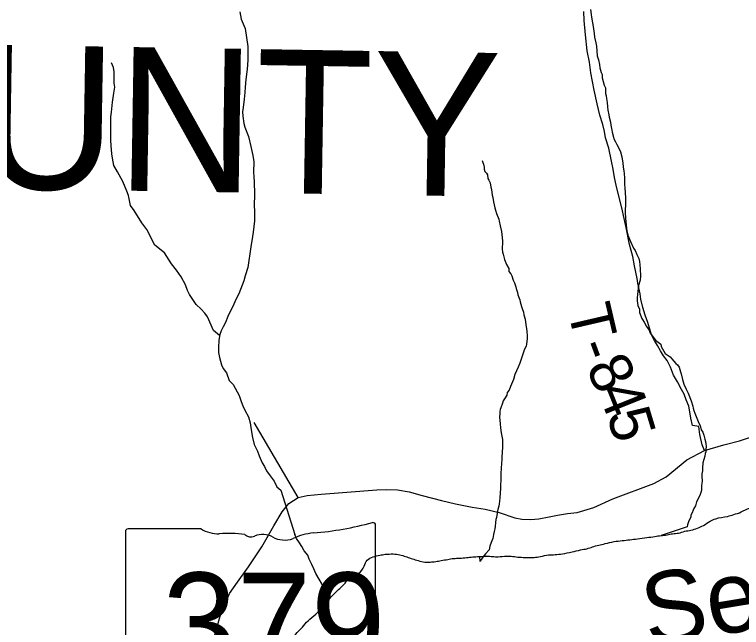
# Model space of a CAD drawing. Extents: x 0 to 191, y 0 to 55.
# Drawn here: x 149.0114 to 149.4907, y 21.5453 to 21.9492 of the extents above; entities that cross this region are included whole.
import ezdxf

# ---------------------------------------------------------------- set-up
doc = ezdxf.new("R2010")
doc.units = 0
for name, color, linetype in [('GM_X_County_Text', 7, 'Continuous'), ('GM_X_Minor_River', 7, 'Continuous'), ('GM_X_Minor_River_Text', 7, 'Continuous'), ('GM_X_State_Location', 7, 'Continuous'), ('GM_X_State_Route', 7, 'Continuous'), ('GM_X_State_Shield', 7, 'Continuous'), ('GM_X_Township_Road', 7, 'Continuous'), ('GM_X_Township_Road_Text', 7, 'Continuous')]:
    doc.layers.add(name, color=color, linetype=linetype)

msp = doc.modelspace()

# ---------------------------------------------------------------- linework, layer by layer
at = {"layer": 'GM_X_Minor_River'}
for points in [[(149.39103, 21.9526), (149.39158, 21.94918), (149.39176, 21.94747), (149.39249, 21.94386), (149.39285, 21.94139), (149.39358, 21.93682), (149.39376, 21.93435), (149.39468, 21.93055), (149.39505, 21.92846), (149.39558, 21.922), (149.39632, 21.91934), (149.39706, 21.91629), (149.39723, 21.9142), (149.39816, 21.91097), (149.39872, 21.90964), (149.3989, 21.90755), (149.40019, 21.90279), (149.40094, 21.90089), (149.40093, 21.89975), (149.40111, 21.89709), (149.40147, 21.89557), (149.40165, 21.89386), (149.40202, 21.89119), (149.40238, 21.88834), (149.40255, 21.88625), (149.40329, 21.88321), (149.40347, 21.8815), (149.40421, 21.87827), (149.40458, 21.87637), (149.40512, 21.87313), (149.40549, 21.87161), (149.40623, 21.86838), (149.4066, 21.86724), (149.40754, 21.86533), (149.40848, 21.86362), (149.40942, 21.86209), (149.41091, 21.85866), (149.41184, 21.85543), (149.41238, 21.85125), (149.41274, 21.84878), (149.41311, 21.84593), (149.41329, 21.8446), (149.41346, 21.84118), (149.41364, 21.84004), (149.41362, 21.83681), (149.4138, 21.83548), (149.41396, 21.8313), (149.41413, 21.82883), (149.4141, 21.82351), (149.41389, 21.82067), (149.41388, 21.81877), (149.41423, 21.81497), (149.41476, 21.80813), (149.41513, 21.80661), (149.41568, 21.80394), (149.41755, 21.79975), (149.41942, 21.79537), (149.42055, 21.79366), (149.42167, 21.79118), (149.42298, 21.78851), (149.42354, 21.78642), (149.42371, 21.78433), (149.42388, 21.78167), (149.42404, 21.77673), (149.42384, 21.77427), (149.42286, 21.77067), (149.42266, 21.76858), (149.42207, 21.76478), (149.42186, 21.76251)], [(149.15985, 21.95111), (149.16068, 21.94618), (149.16342, 21.93995), (149.16529, 21.9282), (149.16523, 21.91927), (149.16476, 21.91318), (149.16391, 21.90633), (149.16341, 21.90138), (149.16327, 21.89796), (149.16277, 21.8934), (149.1621, 21.88788), (149.16176, 21.88502), (149.16199, 21.88217), (149.16263, 21.87743), (149.16323, 21.87497), (149.16559, 21.86893), (149.1672, 21.8623), (149.16842, 21.85643), (149.16905, 21.85226), (149.16896, 21.84542), (149.16919, 21.84238), (149.16943, 21.83896), (149.16955, 21.83079), (149.16928, 21.82319), (149.16952, 21.81978), (149.16962, 21.81332), (149.16878, 21.80589), (149.16826, 21.80285), (149.16722, 21.79618), (149.16515, 21.78248), (149.16352, 21.77713), (149.16263, 21.7737), (149.15935, 21.76511), (149.15713, 21.76109), (149.15549, 21.75726), (149.15401, 21.75439), (149.15199, 21.75019), (149.15035, 21.74636), (149.14888, 21.74349), (149.14759, 21.74081), (149.14668, 21.73833), (149.14616, 21.73471), (149.14586, 21.72977), (149.14591, 21.72654), (149.14652, 21.72313), (149.14773, 21.7184), (149.1489, 21.71594), (149.15102, 21.71312), (149.1528, 21.70802), (149.15549, 21.7054), (149.15938, 21.69823), (149.16076, 21.69426), (149.16193, 21.69143), (149.1633, 21.68841), (149.16564, 21.68407), (149.16664, 21.68009), (149.16725, 21.67706), (149.16767, 21.67422), (149.1683, 21.67043), (149.16931, 21.66588), (149.17145, 21.66154), (149.17264, 21.65833), (149.17459, 21.6538), (149.17614, 21.65135), (149.17751, 21.64852), (149.17983, 21.64513), (149.18253, 21.64175), (149.18429, 21.63797), (149.18697, 21.63573), (149.1962, 21.60661)], [(149.14658, 21.73764), (149.14248, 21.74093), (149.13856, 21.75), (149.13682, 21.75244), (149.13432, 21.75507), (149.13106, 21.75806), (149.1268, 21.76465), (149.12544, 21.76729), (149.12406, 21.77107), (149.12133, 21.77635), (149.11824, 21.78068), (149.11496, 21.78501), (149.11013, 21.79216), (149.10381, 21.7972), (149.09855, 21.80757), (149.09527, 21.8119), (149.09023, 21.82019), (149.08791, 21.82338), (149.08649, 21.83001), (149.0855, 21.83285), (149.08276, 21.83927), (149.07926, 21.84568), (149.07693, 21.84964), (149.07591, 21.85457), (149.07549, 21.85741), (149.07504, 21.86291), (149.0748, 21.86633), (149.07488, 21.87355), (149.07476, 21.88172), (149.07528, 21.88496), (149.07594, 21.89142), (149.0768, 21.89751), (149.0775, 21.90132), (149.07708, 21.90398), (149.07698, 21.91158), (149.07655, 21.91442), (149.07519, 21.91744)], [(149.3198, 21.85301), (149.32017, 21.85168), (149.32054, 21.85054), (149.32091, 21.84864), (149.32109, 21.84731), (149.32146, 21.84578), (149.32259, 21.84464), (149.32315, 21.84349), (149.32352, 21.84121), (149.32408, 21.84007), (149.32502, 21.83835), (149.32538, 21.8355), (149.32575, 21.83398), (149.32629, 21.83018), (149.32666, 21.82866), (149.32721, 21.82581), (149.32795, 21.82182), (149.32851, 21.82029), (149.32906, 21.8182), (149.33074, 21.81439), (149.33093, 21.81306), (149.33148, 21.81002), (149.3324, 21.80621), (149.33258, 21.80431), (149.33312, 21.80013), (149.33311, 21.79823), (149.3329, 21.79596), (149.33289, 21.79482), (149.33307, 21.79273), (149.33344, 21.79121), (149.33437, 21.78778), (149.33567, 21.78455), (149.33717, 21.78188), (149.33735, 21.77998), (149.33867, 21.77845), (149.33923, 21.77712), (149.34016, 21.77407), (149.34091, 21.77236), (149.34184, 21.76988), (149.34221, 21.76874), (149.34295, 21.76608), (149.34313, 21.76456), (149.34444, 21.76132), (149.34481, 21.75999), (149.34574, 21.75675), (149.34611, 21.75561), (149.34685, 21.75314), (149.34722, 21.75143), (149.34796, 21.74857), (149.34833, 21.74648), (149.34905, 21.74059), (149.34941, 21.73755), (149.3494, 21.73565), (149.34899, 21.73205), (149.34861, 21.73072), (149.34764, 21.72864), (149.34455, 21.71954), (149.34339, 21.71689), (149.34128, 21.71197), (149.34031, 21.70875), (149.33838, 21.70401), (149.3376, 21.70174), (149.33626, 21.70004), (149.33606, 21.69833), (149.33453, 21.69606), (149.33357, 21.69474), (149.33318, 21.69304), (149.33203, 21.69001), (149.33164, 21.68887), (149.33144, 21.68754), (149.33124, 21.6864), (149.33123, 21.68393), (149.3314, 21.68185), (149.33158, 21.67956), (149.33175, 21.67691), (149.3323, 21.67367), (149.33303, 21.66911), (149.3332, 21.66588), (149.333, 21.66436), (149.33278, 21.66057), (149.33276, 21.65772), (149.33256, 21.65582), (149.33236, 21.65355), (149.33215, 21.65013), (149.33194, 21.64709), (149.33192, 21.64481), (149.33191, 21.6431), (149.33188, 21.63874), (149.33168, 21.63684), (149.33147, 21.63399), (149.33126, 21.63077), (149.33106, 21.62849), (149.33086, 21.62678), (149.33066, 21.62526), (149.33007, 21.62299), (149.32968, 21.62052), (149.32909, 21.61787), (149.3287, 21.61654), (149.3285, 21.61445), (149.32829, 21.6118), (149.32809, 21.61028)], [(149.42186, 21.76251), (149.42185, 21.76061), (149.4224, 21.75738), (149.42333, 21.75509), (149.42351, 21.75281), (149.425, 21.749), (149.4265, 21.74653), (149.428, 21.74367), (149.42988, 21.74119), (149.43044, 21.73928), (149.43401, 21.7347), (149.43741, 21.73202), (149.43778, 21.7305), (149.43947, 21.72745), (149.44041, 21.72592), (149.44362, 21.72362), (149.44475, 21.72229), (149.44739, 21.71923), (149.44852, 21.71846), (149.44965, 21.71694), (149.45039, 21.7137), (149.45095, 21.71237), (149.45187, 21.70876), (149.45261, 21.70571), (149.4543, 21.70228), (149.45542, 21.69962), (149.45747, 21.69467), (149.45859, 21.69105), (149.45877, 21.68991), (149.45933, 21.68839), (149.45989, 21.68649), (149.46026, 21.68534), (149.46157, 21.68211), (149.4625, 21.68001), (149.46344, 21.6783), (149.46418, 21.67563), (149.46512, 21.67411), (149.46586, 21.67201), (149.46661, 21.66935), (149.46698, 21.66783), (149.46716, 21.66631), (149.46733, 21.6646), (149.46713, 21.66251), (149.46712, 21.66099), (149.46673, 21.65986), (149.46653, 21.65815), (149.46518, 21.65379), (149.46497, 21.65056), (149.46495, 21.64847), (149.46456, 21.64658), (149.46455, 21.64487), (149.46472, 21.64183), (149.46452, 21.64012), (149.46432, 21.6388), (149.4643, 21.63595), (149.4641, 21.63481), (149.46314, 21.63235), (149.46103, 21.62818), (149.46044, 21.62553), (149.45929, 21.62364), (149.4589, 21.6225), (149.45813, 21.6208), (149.45736, 21.61928), (149.45735, 21.61795), (149.45601, 21.61549), (149.45543, 21.61417), (149.45505, 21.61303), (149.45485, 21.6117), (149.43768, 21.60589)], [(149.32809, 21.61028), (149.32751, 21.60857), (149.32712, 21.60649), (149.32692, 21.60535), (149.32672, 21.60383), (149.32614, 21.60232), (149.32557, 21.60118), (149.32479, 21.59891), (149.32421, 21.59644), (149.32191, 21.5938), (149.32096, 21.59267), (149.32019, 21.59153), (149.31924, 21.5904), (149.31847, 21.5887), (149.31809, 21.59203)], [(149.21905, 21.56414), (149.21965, 21.56581), (149.2172, 21.5683), (149.21551, 21.57078), (149.21383, 21.57459), (149.21214, 21.57707), (149.21007, 21.58088), (149.20877, 21.58393), (149.20746, 21.58679), (149.20558, 21.59041), (149.20465, 21.59288), (149.20239, 21.59574), (149.2007, 21.5986), (149.1992, 21.60108), (149.19732, 21.60394), (149.1962, 21.60661)]]:
    msp.add_lwpolyline(points, dxfattribs=at)
for points in [[(149.43768, 21.60589), (149.44166, 21.6063), (149.44526, 21.60708), (149.44924, 21.60749), (149.45322, 21.60865), (149.45739, 21.60944), (149.46174, 21.6108), (149.46553, 21.61253), (149.47006, 21.61541), (149.47366, 21.61695), (149.48142, 21.61852), (149.48559, 21.61969), (149.49051, 21.62143), (149.496, 21.62393), (149.5013, 21.62529), (149.50566, 21.62627), (149.50926, 21.62648), (149.51325, 21.62651), (149.51723, 21.62711), (149.52121, 21.62751), (149.52384, 21.63189), (149.52514, 21.6357), (149.52587, 21.63988), (149.52603, 21.64387), (149.52714, 21.64767), (149.5292, 21.65148), (149.53317, 21.65379), (149.53677, 21.65476), (149.54055, 21.65668), (149.54414, 21.65917), (149.5481, 21.66243), (149.55168, 21.66587), (149.55527, 21.66893), (149.55924, 21.67123), (149.56321, 21.67316), (149.56792, 21.6768), (149.5717, 21.67929), (149.57605, 21.68178), (149.58172, 21.68524), (149.58719, 21.68907), (149.59172, 21.69309), (149.59607, 21.69596), (149.59983, 21.69978), (149.60435, 21.70494), (149.60679, 21.70856), (149.6098, 21.71276), (149.61186, 21.71676), (149.6143, 21.72076), (149.61522, 21.72475), (149.61633, 21.72837), (149.61763, 21.73293), (149.61817, 21.7373), (149.61833, 21.7411), (149.6183, 21.7449), (149.61847, 21.74888), (149.61843, 21.75401), (149.6186, 21.75762), (149.61895, 21.7618), (149.61948, 21.76655), (149.61983, 21.77129), (149.62036, 21.77718), (149.62165, 21.78232), (149.62257, 21.78707), (149.62517, 21.79468), (149.62779, 21.79925), (149.62947, 21.80306), (149.63172, 21.80801), (149.63453, 21.81353), (149.63639, 21.81848), (149.63768, 21.824), (149.63917, 21.82799), (149.64066, 21.83237), (149.64252, 21.83713), (149.64344, 21.84131), (149.64435, 21.84663), (149.64489, 21.85043), (149.64524, 21.85556), (149.6454, 21.85993), (149.64537, 21.86353), (149.64497, 21.86752), (149.64494, 21.87169), (149.6451, 21.87568), (149.64507, 21.87929), (149.64486, 21.88327), (149.64426, 21.88688), (149.64384, 21.89257), (149.64363, 21.89636), (149.64303, 21.90016), (149.64243, 21.90452), (149.64183, 21.90831), (149.64141, 21.91438), (149.64101, 21.91799), (149.64098, 21.92235), (149.64057, 21.92672), (149.64016, 21.93146), (149.63956, 21.93582), (149.63933, 21.94095)], [(147.57106, 21.67041), (147.59351, 21.65617), (147.61917, 21.64989), (147.64452, 21.63355), (147.66965, 21.62233), (147.69556, 21.60713), (147.72092, 21.58964), (147.74741, 21.57292), (147.77115, 21.59853), (147.76791, 21.57325), (147.79344, 21.55805), (147.81899, 21.54094), (147.84519, 21.5377), (147.87047, 21.5318), (147.89584, 21.51317), (147.92096, 21.53043), (147.94618, 21.53193), (147.97166, 21.55279), (147.99657, 21.5727), (148.01002, 21.54735), (148.03518, 21.5591), (148.05037, 21.58483), (148.07608, 21.59905), (148.10468, 21.60664), (148.13042, 21.61574), (148.15673, 21.62483), (148.18248, 21.63412), (148.20746, 21.64283), (148.23281, 21.65438), (148.25831, 21.64316), (148.28353, 21.6456), (148.30881, 21.63951), (148.33389, 21.63492), (148.35665, 21.60982), (148.38199, 21.59518), (148.40764, 21.59042), (148.43282, 21.57084), (148.45596, 21.5446), (148.48115, 21.52464), (148.50622, 21.52101), (148.5313, 21.51605), (148.55159, 21.49093), (148.57226, 21.46601), (148.59027, 21.44069), (148.61537, 21.43345), (148.64058, 21.40969), (148.66611, 21.39486), (148.69115, 21.39598), (148.71646, 21.38532), (148.73751, 21.36021), (148.76281, 21.35031), (148.78815, 21.33624), (148.81347, 21.3235), (148.8386, 21.31208), (148.86427, 21.30466), (148.89012, 21.29818), (148.91559, 21.29094), (148.94066, 21.28807), (148.96647, 21.28748), (148.99169, 21.28936), (149.01687, 21.29882), (149.04205, 21.30677), (149.06693, 21.31374)], [(147.57106, 21.67041), (147.59351, 21.65617), (147.61917, 21.64989), (147.64452, 21.63355), (147.66965, 21.62233), (147.69556, 21.60713), (147.72092, 21.58964), (147.74741, 21.57292), (147.77115, 21.59853), (147.76791, 21.57325), (147.79344, 21.55805), (147.81899, 21.54094), (147.84519, 21.5377), (147.87047, 21.5318), (147.89584, 21.51317), (147.92096, 21.53043), (147.94618, 21.53193), (147.97166, 21.55279), (147.99657, 21.5727), (148.01002, 21.54735), (148.03518, 21.5591), (148.05037, 21.58483), (148.07608, 21.59905), (148.10468, 21.60664), (148.13042, 21.61574), (148.15673, 21.62483), (148.18248, 21.63412), (148.20746, 21.64283), (148.23281, 21.65438), (148.25831, 21.64316), (148.28353, 21.6456), (148.30881, 21.63951), (148.33389, 21.63492), (148.35665, 21.60982), (148.38199, 21.59518), (148.40764, 21.59042), (148.43282, 21.57084), (148.45596, 21.5446), (148.48115, 21.52464), (148.50622, 21.52101), (148.5313, 21.51605), (148.55159, 21.49093), (148.57226, 21.46601), (148.59027, 21.44069), (148.61537, 21.43345), (148.64058, 21.40969), (148.66611, 21.39486), (148.69115, 21.39598), (148.71646, 21.38532), (148.73751, 21.36021), (148.76281, 21.35031), (148.78815, 21.33624), (148.81347, 21.3235), (148.8386, 21.31208), (148.86427, 21.30466), (148.89012, 21.29818), (148.91559, 21.29094), (148.94066, 21.28807), (148.96647, 21.28748), (148.99169, 21.28936), (149.01687, 21.29882), (149.04205, 21.30677), (149.06705, 21.31377)], [(149.05968, 21.31692), (149.04083, 21.31085), (149.01547, 21.30285), (148.99077, 21.29356), (148.96636, 21.29174), (148.94095, 21.29233), (148.91642, 21.29514), (148.89122, 21.3023), (148.86538, 21.30877), (148.84008, 21.31609), (148.81531, 21.32734), (148.79014, 21.34001), (148.76463, 21.35418), (148.74007, 21.36378), (148.71906, 21.38885), (148.69192, 21.40028), (148.66717, 21.39917), (148.64314, 21.41313), (148.61754, 21.43726), (148.59288, 21.44437), (148.57564, 21.46861), (148.55489, 21.49363), (148.53364, 21.51993), (148.50694, 21.52521), (148.48289, 21.52869), (148.45891, 21.5477), (148.43575, 21.57396), (148.40943, 21.59442), (148.38348, 21.59924), (148.35936, 21.61318), (148.33608, 21.63886), (148.3097, 21.64368), (148.28383, 21.64991), (148.25901, 21.64751), (148.23278, 21.65905), (148.20587, 21.64678), (148.18105, 21.63813), (148.15531, 21.62885), (148.12901, 21.61976), (148.10342, 21.61072), (148.07448, 21.60303), (148.04729, 21.588), (148.03218, 21.5624), (148.01189, 21.55293), (147.99792, 21.57924), (147.96898, 21.5561), (147.94455, 21.5361), (147.91952, 21.53461), (147.89592, 21.5184), (147.87229, 21.53575), (147.84594, 21.5419), (147.82052, 21.54505), (147.79572, 21.56165), (147.77249, 21.57548), (147.77706, 21.61118), (147.7467, 21.57842), (147.72327, 21.5932), (147.69785, 21.61072), (147.6716, 21.62612), (147.64656, 21.6373), (147.62088, 21.65386), (147.5952, 21.66014), (147.57469, 21.67316)], [(149.10959, 21.36284), (149.11222, 21.36665), (149.11465, 21.37103), (149.11785, 21.37542), (149.11953, 21.3798), (149.12197, 21.38361), (149.12478, 21.388), (149.12627, 21.3918), (149.12549, 21.39579), (149.12451, 21.39958), (149.12391, 21.40451), (149.12767, 21.40985), (149.13105, 21.41386), (149.13502, 21.41711), (149.1384, 21.42093), (149.13952, 21.42454), (149.13968, 21.42853), (149.1406, 21.43252), (149.14304, 21.43634), (149.14112, 21.44012), (149.13843, 21.4439), (149.13651, 21.44787), (149.13914, 21.4515), (149.14101, 21.45512), (149.14364, 21.45893), (149.14913, 21.46125), (149.15292, 21.4626), (149.15745, 21.46586), (149.15989, 21.46967), (149.16043, 21.47385), (149.16059, 21.47784), (149.16189, 21.48183), (149.16754, 21.48756), (149.17074, 21.49176), (149.17337, 21.49577), (149.1758, 21.49996), (149.18067, 21.50986), (149.18216, 21.51386), (149.18345, 21.51937), (149.18549, 21.52527), (149.18755, 21.53003), (149.19094, 21.53423), (149.1947, 21.53824), (149.19771, 21.54187), (149.20129, 21.5455), (149.20487, 21.5497), (149.20996, 21.5541), (149.21505, 21.55926), (149.21825, 21.56326), (149.22314, 21.56861), (149.22673, 21.57186), (149.23012, 21.57549), (149.2337, 21.57912), (149.23843, 21.58105), (149.24181, 21.58563), (149.24387, 21.58963), (149.24784, 21.59174), (149.2522, 21.59291), (149.2558, 21.5935), (149.26092, 21.59373), (149.26548, 21.59319), (149.26909, 21.59207), (149.27651, 21.58965), (149.28069, 21.58854), (149.28543, 21.58838), (149.28904, 21.58878), (149.29264, 21.58938), (149.297, 21.59017), (149.30079, 21.59076), (149.30496, 21.59098), (149.30932, 21.59138), (149.31349, 21.59179), (149.31767, 21.59201), (149.32241, 21.59223), (149.32658, 21.59207), (149.33019, 21.5919), (149.33569, 21.59232), (149.33987, 21.59215), (149.34442, 21.59161), (149.34898, 21.59146), (149.35391, 21.59149), (149.35808, 21.59208), (149.36339, 21.59307), (149.36775, 21.59329), (149.37268, 21.59389), (149.37893, 21.59507), (149.38462, 21.59643), (149.38879, 21.59722), (149.39238, 21.59838), (149.40072, 21.60053), (149.40678, 21.60189), (149.41209, 21.6025), (149.41702, 21.6031), (149.42214, 21.6037), (149.4282, 21.6045), (149.43351, 21.6053), (149.43768, 21.60589)]]:
    msp.add_spline(points, degree=3, dxfattribs=at)
at = {"layer": 'GM_X_State_Route'}
msp.add_lwpolyline([(149.14328, 21.53964), (149.14789, 21.55587), (149.15041, 21.56136), (149.15304, 21.56761), (149.15831, 21.57517), (149.16565, 21.58526), (149.17443, 21.59853), (149.18232, 21.61235), (149.18792, 21.62145), (149.19219, 21.62694), (149.19844, 21.63088), (149.20437, 21.63231), (149.21358, 21.63319), (149.25021, 21.63593), (149.25679, 21.63626), (149.26391, 21.63593), (149.27159, 21.63461), (149.28014, 21.6322), (149.29297, 21.62902), (149.30219, 21.62672), (149.31304, 21.62463), (149.32171, 21.62321), (149.33092, 21.62101), (149.34134, 21.61761), (149.34583, 21.61674), (149.35176, 21.61641), (149.35702, 21.61685), (149.36393, 21.61827), (149.36941, 21.61937), (149.37599, 21.62036), (149.38224, 21.62112), (149.39332, 21.6243), (149.40582, 21.63001), (149.43291, 21.64009), (149.44091, 21.64448), (149.45462, 21.65578), (149.46635, 21.66181), (149.47908, 21.66565), (149.48927, 21.66839), (149.502, 21.67245)], dxfattribs=at)
at = {"layer": 'GM_X_State_Shield'}
for p, q in [((149.24938, 21.56041), (149.24938, 21.61276)), ((149.08459, 21.60856), (149.08459, 21.5085)), ((149.13447, 21.61028), (149.08621, 21.61028)), ((149.24937, 21.56043), (149.24938, 21.56041))]:
    msp.add_line(p, q, dxfattribs=at)
for centre, major_axis, start_param, end_param in [((149.19068, 21.74669), (0.17476, 0), 4.814394, 5.042369), ((149.24756, 21.61297), (0.00183, 0), 6.141152, 7.989035), ((149.08648, 21.60877), (0.00191, 0), 1.712693, 3.28349), ((149.14597, 21.62189), (0.01852, 0), 4.042523, 4.731795), ((149.15211, 21.5541), (0.06648, 0), 1.404758, 1.657858), ((149.21297, 21.57972), (0.03516, 0), 1.699011, 2.107814), ((149.1672, 21.60929), (0.00534, 0), 3.836095, 5.185415), ((149.17504, 21.59772), (0.01111, 0), 0.950623, 2.079405), ((149.18938, 21.61358), (0.01336, 0), 4.081561, 5.145723), ((149.24743, 21.56021), (0.00196, 0), 5.05454, 6.418171), ((149.24896, 21.55657), (0.00284, 0), 1.883978, 3.671073), ((149.2309, 21.54995), (0.01704, 0), 5.934695, 6.695948)]:
    msp.add_ellipse(centre, major_axis=major_axis, ratio=0.8, start_param=start_param, end_param=end_param, dxfattribs=at)
at = {"layer": 'GM_X_Township_Road'}
msp.add_line((149.19844, 21.63088), (149.16925, 21.68042), dxfattribs=at)
msp.add_lwpolyline([(149.46635, 21.66181), (149.46471, 21.66576), (149.46328, 21.67245), (149.46252, 21.67771), (149.45831, 21.67835), (149.4573, 21.68328), (149.45668, 21.68746), (149.45588, 21.69106), (149.45412, 21.69522), (149.45293, 21.699), (149.45118, 21.70221), (149.44846, 21.70712), (149.44593, 21.71165), (149.44378, 21.71676), (149.44164, 21.7213), (149.43932, 21.72431), (149.43719, 21.72771), (149.43524, 21.7311), (149.4333, 21.7345), (149.43136, 21.73809), (149.42898, 21.74623), (149.42721, 21.75115), (149.42563, 21.75626), (149.42442, 21.76176), (149.42381, 21.76517), (149.42239, 21.77219), (149.42198, 21.77522), (149.42017, 21.78356), (149.41895, 21.78982), (149.41695, 21.79777), (149.41473, 21.80896), (149.41333, 21.81483), (149.41172, 21.82185), (149.40991, 21.82961), (149.40812, 21.83682), (149.40691, 21.84193), (149.40609, 21.84743), (149.40508, 21.85255), (149.40326, 21.86108), (149.40109, 21.86789), (149.40028, 21.87225), (149.39927, 21.8768), (149.3973, 21.88286), (149.3955, 21.89044), (149.39348, 21.89935), (149.39126, 21.91072), (149.39041, 21.91793), (149.38899, 21.92533), (149.38791, 21.93595), (149.38704, 21.94525), (149.38678, 21.95133)], dxfattribs=at)

# ---------------------------------------------------------------- texts
at = {"layer": 'GM_X_County_Text'}
msp.add_text('MONROE COUNTY', height=0.094697, rotation=359.0616, dxfattribs=at).set_placement((148.19166, 21.8478))
at = {"layer": 'GM_X_Minor_River_Text'}
msp.add_text('Seneca', height=0.047346, rotation=9.3726, dxfattribs=at).set_placement((149.42913, 21.53248))
at = {"layer": 'GM_X_State_Location'}
for s, p in [('s', (149.16514, 21.55187)), ('r', (149.16513, 21.55187))]:
    msp.add_text(s, height=0.0000947, dxfattribs=at).set_placement(p)
at = {"layer": 'GM_X_State_Shield'}
msp.add_text('379', height=0.065918, dxfattribs=at).set_placement((149.10883, 21.51555))
at = {"layer": 'GM_X_Township_Road_Text'}
for s, rotation, p in [('T', 283.0769, (149.37588, 21.75512)), ('-', 290.1828, (149.38178, 21.73074)), ('8', 297.778, (149.38748, 21.71604)), ('4', 291.9193, (149.39531, 21.70125)), ('5', 286.794, (149.40162, 21.68565))]:
    msp.add_text(s, height=0.02841, rotation=rotation, dxfattribs=at).set_placement(p)

doc.saveas('drawing.dxf')
